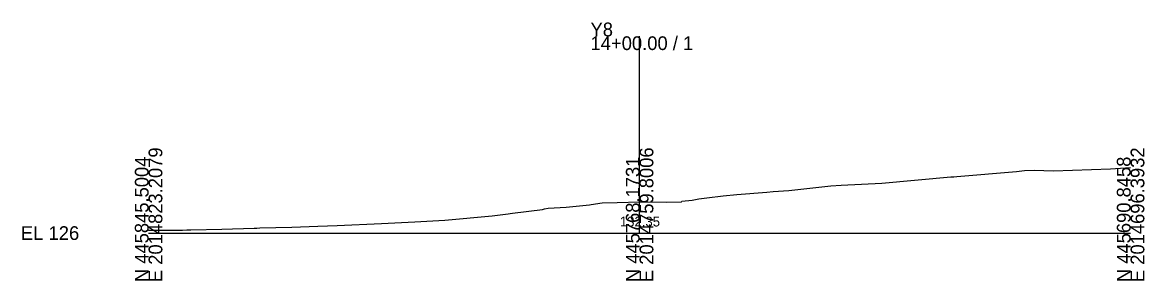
# Model space of a CAD drawing. Extents: x -26 to 1403, y -10 to 8043.
# Drawn here: x -25.7 to 202.8, y 7990.3 to 8043 of the extents above; entities that cross this region are included whole.
import ezdxf

# ---------------------------------------------------------------- set-up
doc = ezdxf.new("R2010")
doc.units = 0
for name, color, linetype in [('Default', 7, 'Continuous'), ('Exist Cross Section Cell', 7, 'Continuous'), ('Exist XS Center Line Elevation Label', 7, 'Continuous'), ('Exist XS Ground Line', 7, 'Continuous')]:
    doc.layers.add(name, color=color, linetype=linetype)

msp = doc.modelspace()

# ---------------------------------------------------------------- linework, layer by layer
at = {"layer": 'Exist Cross Section Cell'}
for p, q in [((100, 8000), (100, 8040.15)), ((0, 8000), (100, 8000)), ((100, 8000), (200, 8000))]:
    msp.add_line(p, q, dxfattribs=at)
at = {"layer": 'Exist XS Ground Line'}
msp.add_lwpolyline([(0, 8000.6), (0.72, 8000.6), (6.88, 8000.63), (7.82, 8000.64), (8.6, 8000.66), (14.93, 8000.81), (21.53, 8001.02), (22.04, 8001.03), (22.65, 8001.05), (29.14, 8001.21), (34.46, 8001.41), (38.42, 8001.57), (47.4, 8001.93), (54.2, 8002.28), (60.33, 8002.62), (69.97, 8003.53), (73.25, 8003.96), (73.65, 8004.03), (74.1, 8004.06), (80.2, 8004.81), (80.62, 8004.94), (81.41, 8005.1), (85.05, 8005.27), (89.8, 8005.77), (90.15, 8005.84), (92.35, 8006.18), (95.45, 8006.26), (100, 8006.35), (100.55, 8006.36), (105.4, 8006.32), (108.53, 8006.37), (108.59, 8006.51), (110.68, 8006.73), (112.05, 8006.98), (113.67, 8007.2), (117.01, 8007.57), (119.79, 8007.87), (125.91, 8008.36), (127.23, 8008.48), (130.39, 8008.71), (138.92, 8009.64), (141.07, 8009.76), (149.36, 8010.19), (163.36, 8011.45), (164, 8011.5), (164.61, 8011.54), (176.73, 8012.6), (178.38, 8012.8), (180.38, 8012.85), (184.3, 8012.69), (195.9, 8013.14), (200, 8013.38)], dxfattribs=at)

# ---------------------------------------------------------------- texts
at = {"layer": 'Default'}
msp.add_text('-', height=0.0001, dxfattribs=at).set_placement((0, 8000))
at = {"layer": 'Exist Cross Section Cell'}
for s, p in [('Y8', (90, 8040.15)), ('14+00.00 / 1', (90, 8037.35)), ('EL 126', (-26, 7998.6))]:
    msp.add_text(s, height=2.8, dxfattribs=at).set_placement(p)
for s, p in [('E 2014823.2079', (2.8, 7990)), ('E 2014759.8006', (102.8, 7990)), ('E 2014696.3932', (202.8, 7990)), ('N 445845.5004', (0, 7990)), ('N 445768.1731', (100, 7990)), ('N 445690.8458', (200, 7990))]:
    msp.add_text(s, height=2.8, rotation=90, dxfattribs=at).set_placement(p)
at = {"layer": 'Exist XS Center Line Elevation Label'}
msp.add_text('132.35', height=2, dxfattribs=at).set_placement((95.98, 8001.35))

doc.saveas('drawing.dxf')
